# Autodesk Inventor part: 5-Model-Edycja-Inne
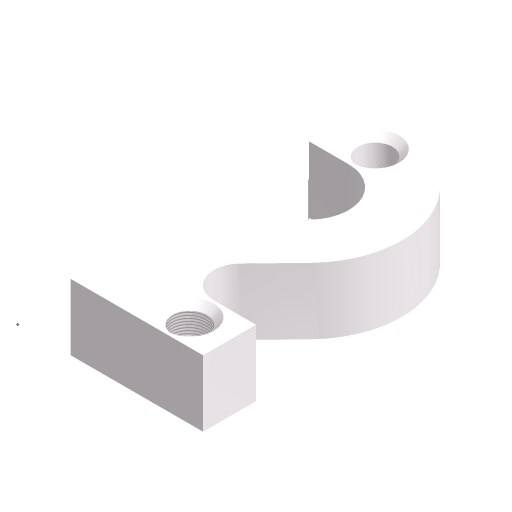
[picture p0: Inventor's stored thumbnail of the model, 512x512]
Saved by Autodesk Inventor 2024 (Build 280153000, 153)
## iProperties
Company: ATC
Shininess: 21.0
Length Units: 11269
Angle Units: 11279
Time Units: 11290
Mass Units: 11283
Compacted: True
Created: 2023-03
Part Number: 5-Model-Edycja-Inne
Document SubType Name: Modeling
Designer: Andrzej Jaskulski
Material: Kurs-AJ
Density: 1 g/cm^3
Appearance: Kurs-AJ
Checked By: A.J.
Engr Approved By: Andrzej Jaskulski
Mfg Approved By: Andrzej Jaskulski
Authority: A.J.
Density: 0.0
Volumn: 0.0
Area: 0.0
PropertySet Name: Model Information
Control State: 0
Master: False
Checked Out: False
Title: A.J.: Kurs R2024-MEP
Author: Andrzej Jaskulski
Revision Number: 1/24
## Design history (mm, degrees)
sketch "Zarys dwójki"
  geometry: L1 (140, 0.063)-(40, 0.063) reference; L2 (140, 0.063)-(140, 40.063); L3 (140, 40.063)-(61.086, 40.063); L4 (61.086, 40.063)-(120.354, 101.437); L5 (91.58, 129.223)-(40, 75.81); L6 (40, 75.81)-(40, 0.063); L7 (40, 180.063)-(40, 213.309); L8 (40, 180.063)-(70, 180.063); A1 r 30 centre (70, 150.063) between (91.58, 129.223) and (70, 180.063); A2 r 70 centre (70, 150.063) between (120.354, 101.437) and (40, 213.309)
  constraints: 16 end point, 5 tangent, 4 point on circle, 3 perpendicular, 2 centre point, 1 coincident, 1 collinear, 1 horizontal, 1 parallel, 1 vertical, 1 other
  dimensions: "d0" = 46 deg angle of L4 L3; "d1" = 30 radius of A1; "d2" = 70 radius of A2; "d15" = 150 distance from line of A1.centre L1; "d16" = 40 distance of L1.start L2.end; "d17" = 100 distance of L1.start L1.end
extrude "Dwójka" new body sketch "Zarys dwójki" distance "d3" = 50; taper "d4" = 0 deg
node "Oś walca"
sketch "Oś otworu 1"
  geometry: L1 (108.203, 40.063)-(140, 40.063) reference; L2 (140, 40.063)-(140, 0.063) reference; 1 further point
  dimensions: "d18" = 20 distance from line of L1 point (110, 20.063); "d19" = 30 distance from line of point (110, 20.063) L2
hole "Oryginał" sketch "Oś otworu 1" at (110, 20.063) diameter "d7" = 26; stored, may be unused: countersink angle "d9" = 90 deg, drill point angle "d32" = 118 deg; dims "d8" = 36, "d27" = 12, "d29" = 15, "d31" = 45
sketch "Oś otworu 2"
  geometry: 2 further points
  constraints: 1 vertical alignment
  dimensions: "d14" = 50 distance of point (131.422, -23.545) point (131.422, 26.455)
hole "Kopia" sketch "Oś otworu 2" at (131.422, 26.455) diameter "d13" = 26 (= d7); stored, may be unused: countersink angle "d11" = 90 deg (= d9), drill point angle "d56" = 118 deg; dims "d10" = 12 (= d27), "d12" = 36 (= d8), "d58" = 15, "d60" = 45
node "Bryła1"
node "Korpusy bryłowe"
node "Korpusy powierzchniowe"
fillet "Zaokrąglenie" dims "d6" = 20
feature "Gwint" dims "d42" = 10, "d43" = 0
other parameters: "d5" = 90 deg
